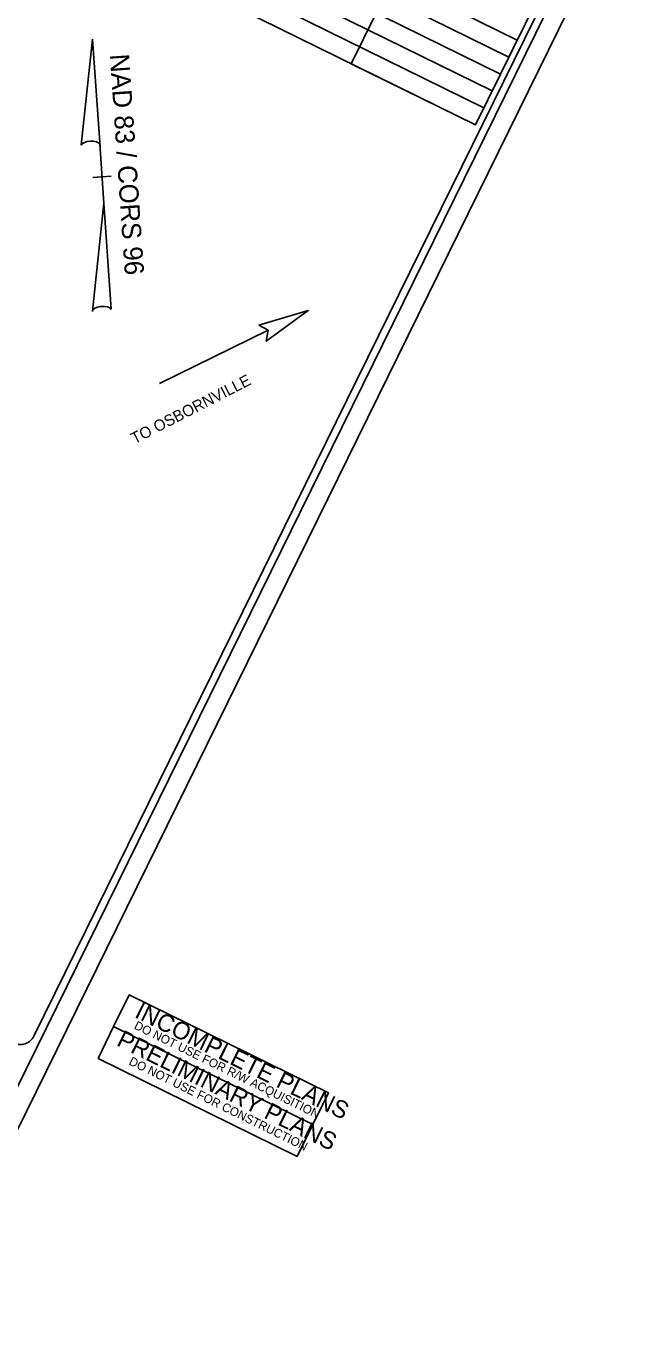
# Model space of a CAD drawing. Extents: x 1428128 to 1430390, y 857947 to 859822.
# Drawn here: x 1429997 to 1430390, y 858014 to 858882 of the extents above; entities that cross this region are included whole.
import ezdxf

# ---------------------------------------------------------------- set-up
doc = ezdxf.new("R2010")
doc.units = 0
for name, color, linetype in [('Old_Level_1', 7, 'Continuous'), ('Sheet Plot Border Inside CELL', 7, 'Continuous'), ('Sheet Sticker Incomplete CELL', 7, 'Continuous'), ('Sheet Sticker Preliminary CELL', 7, 'Continuous'), ('Sheet Title CELL', 7, 'Continuous')]:
    doc.layers.add(name, color=color, linetype=linetype)

msp = doc.modelspace()

# ---------------------------------------------------------------- linework, layer by layer
at = {"layer": 'Old_Level_1'}
for p, q in [((1430033.6, 858803.27), (1430041.08, 858873.48)), ((1430041.16, 858873.48), (1430041.08, 858873.48)), ((1430041.16, 858873.48), (1430041.08, 858873.48)), ((1430041.16, 858873.48), (1430046.1, 858801.95)), ((1430048.66, 858764.84), (1430045.95, 858804.05)), ((1430046.1, 858801.95), (1430045.96, 858803.97)), ((1430041.47, 858781.78), (1430041.4, 858781.78)), ((1430046.79, 858782.15), (1430041.47, 858781.78)), ((1430041.55, 858781.79), (1430053.52, 858782.62)), ((1430048.66, 858764.84), (1430041.04, 858693.27)), ((1430053.59, 858694.44), (1430048.66, 858764.84)), ((1430157.5, 858680.58), (1430085.44, 858645.21))]:
    msp.add_line(p, q, dxfattribs=at)
msp.add_lwpolyline([(1430151.23, 858683.98), (1430184.09, 858693.64), (1430156.27, 858673.3), (1430157.5, 858680.58)], close=True, dxfattribs=at)
for centre, start_param, end_param in [((1430039.84, 858802.95), 0.216388, 2.908219), ((1430047.4, 858693.46), 0.201328, 3.141593)]:
    msp.add_ellipse(centre, major_axis=(6.33, 0.39), ratio=0.461098, start_param=start_param, end_param=end_param, dxfattribs=at)
at = {"layer": 'Sheet Plot Border Inside CELL'}
msp.add_lwpolyline([(1428428.74, 858750.16), (1429924.03, 858014.39), (1430389.86, 858961.09), (1428894.57, 859696.85)], close=True, dxfattribs=at)
at = {"layer": 'Sheet Sticker Incomplete CELL'}
msp.add_lwpolyline([(1430055.14, 858219.2), (1430065.51, 858240.28), (1430197.41, 858175.38), (1430187.03, 858154.3)], close=True, dxfattribs=at)
at = {"layer": 'Sheet Sticker Preliminary CELL'}
msp.add_lwpolyline([(1430044.76, 858198.11), (1430055.14, 858219.2), (1430187.03, 858154.3), (1430176.66, 858133.21)], close=True, dxfattribs=at)
at = {"layer": 'Sheet Title CELL'}
for points in [[(1430070.16, 858982.94), (1430316.91, 858861.53), (1430322.43, 858872.75), (1430075.68, 858994.16)], [(1430059.12, 858960.5), (1430305.86, 858839.09), (1430311.38, 858850.3), (1430064.65, 858971.71)], [(1430262.22, 858958.09), (1430212.55, 858857.15), (1430294.83, 858816.67), (1430361.06, 858951.26)], [(1429922.77, 858040.15), (1430368.69, 858946.37)], [(1430002.17, 858212.83), (1430362, 858944.11)], [(1430048.09, 858938.08), (1430294.83, 858816.67), (1430300.35, 858827.87), (1430053.6, 858949.3)]]:
    msp.add_lwpolyline(points, dxfattribs=at)
msp.add_arc((1429993.22, 858217.29), 10, 243.80011, 333.80011, dxfattribs=at)

# ---------------------------------------------------------------- texts
at = {"layer": 'Old_Level_1'}
for s, height, rotation, p in [('NAD 83 / CORS 96', 12.75, 273.94759, (1430052.55, 858863.25)), ('TO OSBORNVILLE', 7.5, 27.18449, (1430069.02, 858605.01))]:
    msp.add_text(s, height=height, rotation=rotation, dxfattribs=at).set_placement(p)
at = {"layer": 'Sheet Sticker Incomplete CELL'}
for s, height, p in [('INCOMPLETE PLANS', 11.52, (1430068.33, 858225.74)), ('DO NOT USE FOR R/W ACQUISITION', 5.76, (1430068.18, 858218.07))]:
    msp.add_text(s, height=height, rotation=333.80011, dxfattribs=at).set_placement(p)
at = {"layer": 'Sheet Sticker Preliminary CELL'}
for s, height, p in [('PRELIMINARY PLANS', 11.52, (1430056.4, 858207.04)), ('DO NOT USE FOR CONSTRUCTION', 5.76, (1430064.75, 858194.35))]:
    msp.add_text(s, height=height, rotation=333.80011, dxfattribs=at).set_placement(p)

doc.saveas('drawing.dxf')
